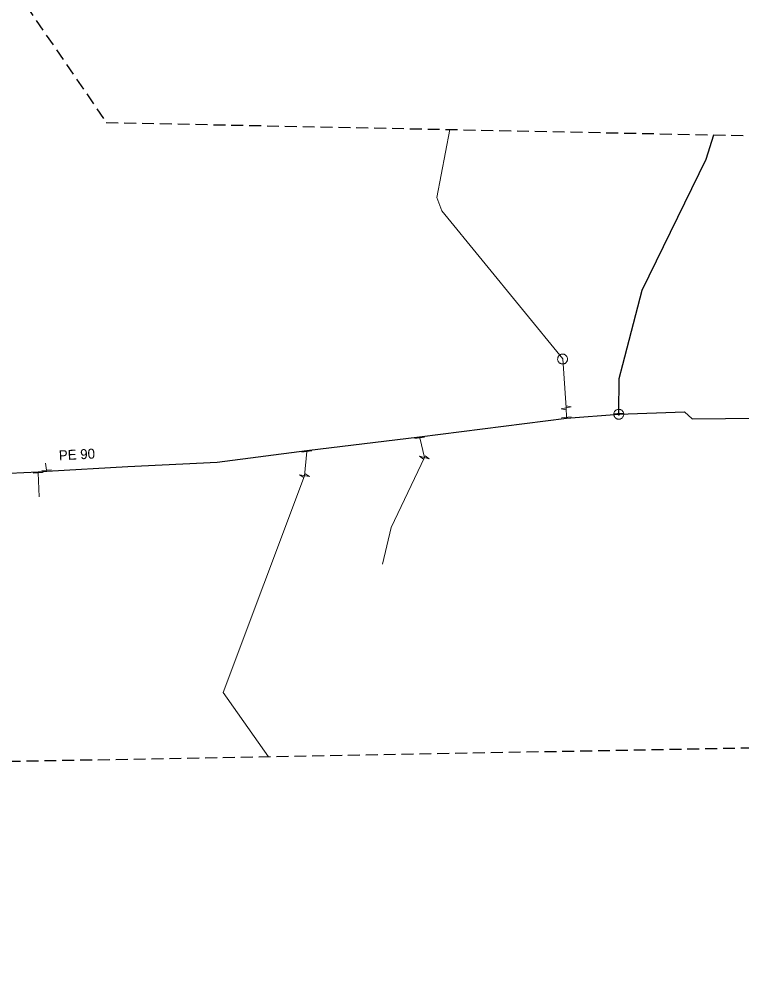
# Model space of a CAD drawing. Extents: x -692311 to -690519, y -971696 to -970899.
# Drawn here: x -691350.6 to -691277.8, y -971307 to -971210.6 of the extents above; entities that cross this region are included whole.
import ezdxf

# ---------------------------------------------------------------- set-up
doc = ezdxf.new("R2010")
doc.units = 0
doc.header["$LTSCALE"] = 0.4
doc.linetypes.add('MEDIUM_DASHED', pattern=[4.5, 3, -1.5])
for name, color, linetype, lineweight in [('1', 7, 'MEDIUM_DASHED', 25), ('13', 7, 'Continuous', 13), ('14', 7, 'Continuous', 13), ('17', 7, 'Continuous', 25), ('23', 7, 'Continuous', 13), ('34', 7, 'Continuous', 13), ('47', 7, 'Continuous', 13)]:
    doc.layers.add(name, color=color, linetype=linetype, lineweight=lineweight)

msp = doc.modelspace()

# ---------------------------------------------------------------- linework, layer by layer
at = {"layer": '1'}
msp.add_lwpolyline([(-691582.607, -971118.48), (-691415.135, -971114.294), (-691341.865, -971221.058), (-691239.288, -971223.151), (-691166.019, -971275.486), (-690967.145, -971283.86), (-690879.221, -971315.261), (-690772.457, -971417.838), (-690699.188, -971434.585), (-690602.891, -971597.872), (-690519.155, -971629.273), (-690531.715, -971696.262), (-690636.386, -971646.02), (-690749.43, -971493.201), (-690789.205, -971468.08), (-690914.809, -971369.69), (-690979.705, -971342.475), (-691195.326, -971327.822), (-691262.316, -971283.86), (-691377.453, -971285.953), (-691463.283, -971177.096)], dxfattribs=at)
at = {"layer": '13'}
for p, q in [((-691310.278, -971252.84), (-691309.811, -971254.826)), ((-691321.656, -971254.212), (-691321.894, -971256.664)), ((-691347.874, -971256.113), (-691347.977, -971255.412)), ((-691348.725, -971256.374), (-691348.616, -971258.784))]:
    msp.add_line(p, q, dxfattribs=at)
for points in [[(-691295.859, -971244.879), (-691308.05, -971229.96), (-691308.55, -971228.609), (-691307.235, -971221.764)], [(-691295.502, -971250.775), (-691295.509, -971249.82), (-691295.859, -971244.879)], [(-691309.811, -971254.826), (-691313.14, -971261.899), (-691314.02, -971265.59)], [(-691321.894, -971256.664), (-691330.096, -971278.509), (-691325.51, -971285.009)]]:
    msp.add_lwpolyline(points, dxfattribs=at)
at = {"layer": '14'}
for p, q in [((-691295.489, -971250.87), (-691295.502, -971250.775)), ((-691290.219, -971250.469), (-691290.223, -971250.375)), ((-691310.289, -971252.75), (-691310.278, -971252.84)), ((-691321.67, -971254.109), (-691321.656, -971254.212)), ((-691348.73, -971256.27), (-691348.725, -971256.374)), ((-691347.87, -971256.199), (-691347.874, -971256.113))]:
    msp.add_line(p, q, dxfattribs=at)
at = {"layer": '17'}
for points in [[(-691389.879, -971221.199), (-691389.609, -971221.64), (-691388.41, -971223.8), (-691383.59, -971231.46), (-691379.149, -971240.359), (-691377.899, -971242.73), (-691375.89, -971246), (-691373.34, -971248.92), (-691370.18, -971251.46), (-691367.43, -971253.25), (-691364.17, -971255.079), (-691361.03, -971256.21), (-691357.44, -971256.66), (-691348.73, -971256.27), (-691347.87, -971256.199), (-691339.71, -971255.75), (-691330.699, -971255.289), (-691321.67, -971254.109), (-691310.289, -971252.75), (-691295.489, -971250.87), (-691290.219, -971250.469)], [(-691290.223, -971250.375), (-691290.17, -971246.859), (-691289.805, -971245.456), (-691287.859, -971237.969), (-691281.42, -971224.739), (-691280.642, -971222.307)], [(-691290.219, -971250.469), (-691283.579, -971250.239), (-691282.82, -971250.93), (-691272.739, -971250.84), (-691262.02, -971252.43), (-691257.1, -971253.91), (-691248.399, -971256.96), (-691240.809, -971260.91), (-691230.43, -971267.27), (-691221.359, -971274.879), (-691213.079, -971284), (-691207.69, -971289.53), (-691204.469, -971292.199), (-691187.35, -971297.28), (-691186.899, -971297.289)]]:
    msp.add_lwpolyline(points, dxfattribs=at)
at = {"layer": '23'}
for points in [[(-691295.382, -971244.854), (-691295.39, -971244.801), (-691295.403, -971244.75), (-691295.422, -971244.703), (-691295.446, -971244.655), (-691295.474, -971244.612), (-691295.507, -971244.571), (-691295.544, -971244.534), (-691295.584, -971244.501), (-691295.628, -971244.472), (-691295.674, -971244.448), (-691295.723, -971244.428), (-691295.774, -971244.415), (-691295.825, -971244.406), (-691295.877, -971244.404), (-691295.929, -971244.405), (-691295.982, -971244.414), (-691296.031, -971244.427), (-691296.082, -971244.446), (-691296.127, -971244.468), (-691296.172, -971244.496), (-691296.213, -971244.531), (-691296.25, -971244.568), (-691296.283, -971244.609), (-691296.312, -971244.651), (-691296.335, -971244.698), (-691296.354, -971244.748), (-691296.368, -971244.797), (-691296.376, -971244.849), (-691296.379, -971244.901), (-691296.377, -971244.953), (-691296.369, -971245.005), (-691296.356, -971245.056), (-691296.337, -971245.105), (-691296.314, -971245.152), (-691296.285, -971245.194), (-691296.252, -971245.235), (-691296.216, -971245.273), (-691296.175, -971245.307), (-691296.131, -971245.335)], [(-691296.082, -971244.446), (-691296.127, -971244.468), (-691296.172, -971244.496), (-691296.213, -971244.531), (-691296.25, -971244.568), (-691296.283, -971244.609), (-691296.312, -971244.651), (-691296.335, -971244.698), (-691296.354, -971244.748), (-691296.368, -971244.797), (-691296.376, -971244.849), (-691296.379, -971244.901), (-691296.377, -971244.953), (-691296.369, -971245.005), (-691296.356, -971245.056), (-691296.337, -971245.105), (-691296.314, -971245.152), (-691296.285, -971245.194), (-691296.252, -971245.235), (-691296.216, -971245.273), (-691296.175, -971245.307), (-691296.131, -971245.335), (-691296.086, -971245.359), (-691296.036, -971245.378), (-691295.986, -971245.392), (-691295.933, -971245.4), (-691295.882, -971245.402), (-691295.83, -971245.401), (-691295.779, -971245.392), (-691295.727, -971245.379), (-691295.678, -971245.361), (-691295.632, -971245.337), (-691295.587, -971245.309), (-691295.547, -971245.277), (-691295.51, -971245.238), (-691295.476, -971245.199), (-691295.448, -971245.156), (-691295.423, -971245.108), (-691295.405, -971245.059), (-691295.391, -971245.009)], [(-691296.131, -971245.335), (-691296.086, -971245.359), (-691296.036, -971245.378), (-691295.986, -971245.392), (-691295.933, -971245.4), (-691295.882, -971245.402), (-691295.83, -971245.401), (-691295.779, -971245.392), (-691295.727, -971245.379), (-691295.678, -971245.361), (-691295.632, -971245.337), (-691295.587, -971245.309), (-691295.547, -971245.277), (-691295.51, -971245.238), (-691295.476, -971245.199), (-691295.448, -971245.156), (-691295.423, -971245.108), (-691295.405, -971245.059), (-691295.391, -971245.009), (-691295.384, -971244.957), (-691295.38, -971244.906), (-691295.382, -971244.854), (-691295.39, -971244.801), (-691295.403, -971244.75), (-691295.422, -971244.703), (-691295.446, -971244.655), (-691295.474, -971244.612), (-691295.507, -971244.571), (-691295.544, -971244.534), (-691295.584, -971244.501), (-691295.628, -971244.472), (-691295.674, -971244.448), (-691295.723, -971244.428), (-691295.774, -971244.415), (-691295.825, -971244.406), (-691295.877, -971244.404), (-691295.929, -971244.405), (-691295.982, -971244.414), (-691296.031, -971244.427), (-691296.082, -971244.446)], [(-691295.391, -971245.009), (-691295.384, -971244.957), (-691295.38, -971244.906), (-691295.382, -971244.854)]]:
    msp.add_lwpolyline(points, dxfattribs=at)
at = {"layer": '34'}
for p, q in [((-691295.997, -971250.838), (-691295.005, -971250.712)), ((-691290.722, -971250.392), (-691289.723, -971250.358)), ((-691309.782, -971252.776), (-691310.774, -971252.902)), ((-691321.16, -971254.146), (-691322.151, -971254.276)), ((-691348.225, -971256.351), (-691349.224, -971256.395)), ((-691348.373, -971256.141), (-691347.374, -971256.085))]:
    msp.add_line(p, q, dxfattribs=at)
at = {"layer": '47'}
for p, q in [((-691296.008, -971249.921), (-691295.507, -971250.02)), ((-691309.316, -971254.95), (-691309.725, -971254.644)), ((-691321.391, -971256.748), (-691321.823, -971256.475))]:
    msp.add_line(p, q, dxfattribs=at)
for points in [[(-691296.008, -971249.921), (-691295.009, -971249.718), (-691295.51, -971249.619)], [(-691309.316, -971254.95), (-691310.305, -971254.701), (-691309.896, -971255.007)], [(-691321.391, -971256.748), (-691322.396, -971256.579), (-691321.964, -971256.852)]]:
    msp.add_lwpolyline(points, dxfattribs=at)
for points in [[(-691289.72, -971250.431), (-691289.727, -971250.379), (-691289.739, -971250.328), (-691289.757, -971250.279), (-691289.778, -971250.231), (-691289.806, -971250.186), (-691289.838, -971250.145), (-691289.874, -971250.107), (-691289.914, -971250.073), (-691289.956, -971250.043), (-691290.002, -971250.018), (-691290.051, -971249.997), (-691290.101, -971249.983), (-691290.152, -971249.973), (-691290.204, -971249.969), (-691290.256, -971249.97), (-691290.308, -971249.977), (-691290.359, -971249.989), (-691290.409, -971250.007), (-691290.456, -971250.028), (-691290.501, -971250.056), (-691290.542, -971250.088), (-691290.581, -971250.124), (-691290.615, -971250.164), (-691290.645, -971250.206), (-691290.669, -971250.252), (-691290.69, -971250.301), (-691290.705, -971250.351), (-691290.714, -971250.402), (-691290.718, -971250.454), (-691290.717, -971250.506), (-691290.71, -971250.558), (-691290.698, -971250.609), (-691290.681, -971250.659), (-691290.659, -971250.706), (-691290.631, -971250.751), (-691290.6, -971250.792), (-691290.564, -971250.831), (-691290.524, -971250.865), (-691290.481, -971250.895), (-691290.435, -971250.919), (-691290.386, -971250.94), (-691290.337, -971250.955), (-691290.285, -971250.964), (-691290.233, -971250.968), (-691290.181, -971250.967), (-691290.129, -971250.96), (-691290.078, -971250.948), (-691290.029, -971250.931), (-691289.981, -971250.909), (-691289.936, -971250.881), (-691289.895, -971250.85), (-691289.857, -971250.814), (-691289.823, -971250.774), (-691289.793, -971250.731), (-691289.768, -971250.685), (-691289.747, -971250.636), (-691289.733, -971250.587), (-691289.723, -971250.535), (-691289.719, -971250.483)], [(-691290.137, -971250.462), (-691290.137, -971250.453), (-691290.14, -971250.445), (-691290.143, -971250.438), (-691290.146, -971250.43), (-691290.151, -971250.422), (-691290.156, -971250.416), (-691290.162, -971250.409), (-691290.168, -971250.404), (-691290.176, -971250.399), (-691290.183, -971250.395), (-691290.191, -971250.391), (-691290.199, -971250.389), (-691290.208, -971250.387), (-691290.216, -971250.386), (-691290.225, -971250.387), (-691290.234, -971250.387), (-691290.242, -971250.39), (-691290.249, -971250.393), (-691290.257, -971250.396), (-691290.265, -971250.401), (-691290.271, -971250.406), (-691290.278, -971250.412), (-691290.283, -971250.418), (-691290.289, -971250.426), (-691290.292, -971250.433), (-691290.296, -971250.441), (-691290.298, -971250.449), (-691290.3, -971250.458), (-691290.301, -971250.466), (-691290.3, -971250.475), (-691290.3, -971250.484), (-691290.297, -971250.492), (-691290.294, -971250.499), (-691290.291, -971250.507), (-691290.286, -971250.515), (-691290.282, -971250.521), (-691290.275, -971250.528), (-691290.269, -971250.533), (-691290.261, -971250.539), (-691290.254, -971250.542), (-691290.246, -971250.546), (-691290.238, -971250.548), (-691290.229, -971250.55), (-691290.221, -971250.551), (-691290.212, -971250.55), (-691290.203, -971250.55), (-691290.195, -971250.547), (-691290.188, -971250.544), (-691290.18, -971250.541), (-691290.172, -971250.536), (-691290.166, -971250.532), (-691290.159, -971250.525), (-691290.154, -971250.519), (-691290.149, -971250.511), (-691290.145, -971250.504), (-691290.141, -971250.496), (-691290.139, -971250.488), (-691290.137, -971250.479), (-691290.136, -971250.471)]]:
    msp.add_lwpolyline(points, close=True, dxfattribs=at)

# ---------------------------------------------------------------- texts
at = {"layer": '1'}
msp.add_text('PE 90 ', height=1, rotation=3, dxfattribs=at).set_placement((-691346.617, -971255.117))

doc.saveas('drawing.dxf')
